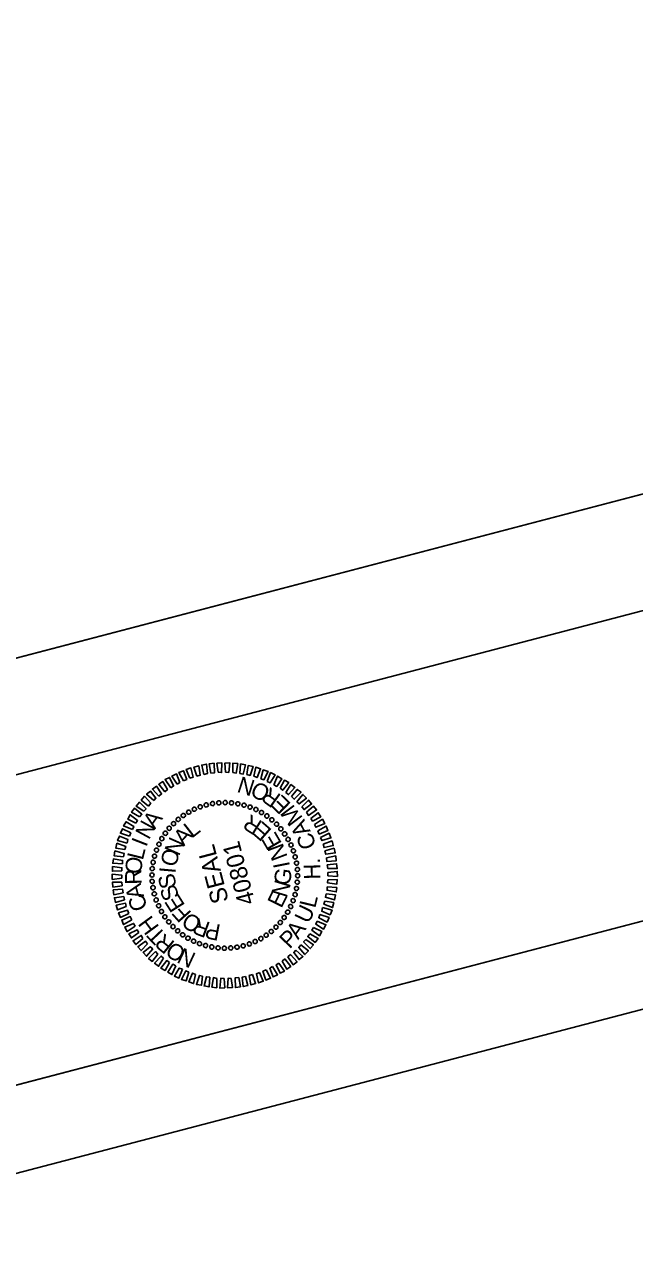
# Model space of a CAD drawing. Extents: x 1366394 to 1367903, y 879298 to 881221.
# Drawn here: x 1366670 to 1366872.8, y 880808.9 to 881221.1 of the extents above; entities that cross this region are included whole.
import ezdxf

# ---------------------------------------------------------------- set-up
doc = ezdxf.new("R2010")
doc.units = 0
for name, color, linetype in [('Exist Property Line Text', 7, 'Continuous'), ('Exist Right of Way Line', 7, 'Continuous'), ('Exist Structure Minor Footbridge Terminator', 7, 'Continuous'), ('Exist Structure Minor Pipes RCP 12 Inch', 7, 'Continuous'), ('Scratch_Level_0', 7, 'Continuous'), ('Scratch_Level_4', 7, 'Continuous')]:
    doc.layers.add(name, color=color, linetype=linetype)

msp = doc.modelspace()

# ---------------------------------------------------------------- linework, layer by layer
at = {"layer": 'Exist Property Line Text'}
msp.add_line((1367471.6, 881221.14), (1366407.53, 880942.29), dxfattribs=at)
at = {"layer": 'Exist Right of Way Line'}
for p, q in [((1367444.83, 881175.34), (1366453.31, 880915.52)), ((1367470.18, 881078.61), (1366478.66, 880818.79))]:
    msp.add_line(p, q, dxfattribs=at)
at = {"layer": 'Exist Structure Minor Footbridge Terminator'}
msp.add_lwpolyline([(1366869.99, 879396.08), (1366503.15, 880795.86), (1367465.82, 881048.15), (1367814.91, 879716.05)], close=True, dxfattribs=at)
at = {"layer": 'Exist Structure Minor Pipes RCP 12 Inch'}
for p, q in [((1366724.52, 880959.08), (1366724.52, 880959.08)), ((1366726.46, 880960.03), (1366726.46, 880960.03)), ((1366728.38, 880960.87), (1366728.38, 880960.87)), ((1366730.42, 880961.49), (1366730.42, 880961.49)), ((1366732.5, 880961.92), (1366732.5, 880961.92)), ((1366734.6, 880962.16), (1366734.6, 880962.16)), ((1366736.67, 880962.29), (1366736.67, 880962.29)), ((1366738.8, 880962.19), (1366738.8, 880962.19)), ((1366740.9, 880961.87), (1366740.9, 880961.87)), ((1366742.98, 880961.45), (1366742.98, 880961.45)), ((1366744.98, 880960.76), (1366744.98, 880960.76)), ((1366746.96, 880959.96), (1366746.96, 880959.96)), ((1366748.79, 880958.97), (1366748.79, 880958.97)), ((1366719.52, 880955.27), (1366719.52, 880955.27)), ((1366721.07, 880956.71), (1366721.07, 880956.71)), ((1366722.72, 880957.98), (1366722.72, 880957.98)), ((1366750.62, 880957.83), (1366750.62, 880957.83)), ((1366752.24, 880956.53), (1366752.24, 880956.53)), ((1366753.8, 880955.06), (1366753.8, 880955.06)), ((1366716.75, 880952.08), (1366716.75, 880952.08)), ((1366718.05, 880953.7), (1366718.05, 880953.7)), ((1366755.24, 880953.51), (1366755.24, 880953.51)), ((1366756.51, 880951.86), (1366756.51, 880951.86)), ((1366713.82, 880946.44), (1366713.82, 880946.44)), ((1366714.62, 880948.42), (1366714.62, 880948.42)), ((1366715.61, 880950.26), (1366715.61, 880950.26)), ((1366757.62, 880950.06), (1366757.62, 880950.06)), ((1366758.57, 880948.11), (1366758.57, 880948.11)), ((1366759.41, 880946.2), (1366759.41, 880946.2)), ((1366712.7, 880942.36), (1366712.7, 880942.36)), ((1366713.13, 880944.44), (1366713.13, 880944.44)), ((1366760.03, 880944.16), (1366760.03, 880944.16)), ((1366760.46, 880942.07), (1366760.46, 880942.07)), ((1366712.29, 880938.13), (1366712.29, 880938.13)), ((1366712.39, 880940.27), (1366712.39, 880940.27)), ((1366736.56, 880938.02), (1366736.56, 880938.02)), ((1366760.7, 880939.98), (1366760.7, 880939.98)), ((1366712.42, 880936.06), (1366712.42, 880936.06)), ((1366712.65, 880933.97), (1366712.65, 880933.97)), ((1366760.73, 880935.77), (1366760.73, 880935.77)), ((1366760.83, 880937.91), (1366760.83, 880937.91)), ((1366713.09, 880931.88), (1366713.09, 880931.88)), ((1366713.71, 880929.85), (1366713.71, 880929.85)), ((1366759.99, 880931.6), (1366759.99, 880931.6)), ((1366760.41, 880933.68), (1366760.41, 880933.68)), ((1366714.55, 880927.93), (1366714.55, 880927.93)), ((1366715.5, 880925.98), (1366715.5, 880925.98)), ((1366757.51, 880925.79), (1366757.51, 880925.79)), ((1366758.5, 880927.62), (1366758.5, 880927.62)), ((1366759.3, 880929.6), (1366759.3, 880929.6)), ((1366716.6, 880924.19), (1366716.6, 880924.19)), ((1366717.87, 880922.54), (1366717.87, 880922.54)), ((1366755.06, 880922.34), (1366755.06, 880922.34)), ((1366756.37, 880923.96), (1366756.37, 880923.96)), ((1366719.31, 880920.98), (1366719.31, 880920.98)), ((1366720.88, 880919.51), (1366720.88, 880919.51)), ((1366722.5, 880918.21), (1366722.5, 880918.21)), ((1366750.39, 880918.07), (1366750.39, 880918.07)), ((1366752.04, 880919.33), (1366752.04, 880919.33)), ((1366753.6, 880920.77), (1366753.6, 880920.77)), ((1366724.32, 880917.07), (1366724.32, 880917.07)), ((1366726.16, 880916.08), (1366726.16, 880916.08)), ((1366728.14, 880915.28), (1366728.14, 880915.28)), ((1366730.14, 880914.59), (1366730.14, 880914.59)), ((1366732.22, 880914.17), (1366732.22, 880914.17)), ((1366734.31, 880913.85), (1366734.31, 880913.85)), ((1366736.45, 880913.75), (1366736.45, 880913.75)), ((1366738.52, 880913.88), (1366738.52, 880913.88)), ((1366740.61, 880914.12), (1366740.61, 880914.12)), ((1366742.7, 880914.55), (1366742.7, 880914.55)), ((1366744.73, 880915.17), (1366744.73, 880915.17)), ((1366746.65, 880916.01), (1366746.65, 880916.01)), ((1366748.6, 880916.96), (1366748.6, 880916.96))]:
    msp.add_line(p, q, dxfattribs=at)
for points in [[(1366729.62, 880971.65), (1366728.87, 880974.71), (1366730.43, 880975.04), (1366730.76, 880971.88)], [(1366731.92, 880972.05), (1366731.36, 880975.1), (1366733, 880975.36), (1366733.1, 880972.13)], [(1366734.4, 880972.35), (1366733.96, 880975.33), (1366735.63, 880975.45), (1366735.48, 880972.25)], [(1366736.8, 880972.37), (1366736.6, 880975.42), (1366738.22, 880975.53), (1366737.88, 880972.27)], [(1366739.23, 880972.3), (1366739.26, 880975.42), (1366740.87, 880975.21), (1366740.35, 880972.06)], [(1366741.54, 880971.94), (1366741.8, 880975.13), (1366743.43, 880974.83), (1366742.69, 880971.76)], [(1366720.7, 880968.4), (1366718.99, 880971.08), (1366720.5, 880971.8), (1366721.6, 880968.95)], [(1366722.82, 880969.45), (1366721.32, 880972.28), (1366722.86, 880972.87), (1366723.88, 880969.94)], [(1366724.97, 880970.35), (1366723.75, 880973.27), (1366725.3, 880973.8), (1366726.06, 880970.76)], [(1366727.28, 880971.05), (1366726.29, 880974.03), (1366727.88, 880974.48), (1366728.4, 880971.36)], [(1366743.94, 880971.61), (1366744.36, 880974.59), (1366746, 880974.3), (1366744.98, 880971.3)], [(1366746.25, 880971.06), (1366746.92, 880974.05), (1366748.48, 880973.49), (1366747.3, 880970.55)], [(1366748.5, 880970.18), (1366749.38, 880973.14), (1366750.98, 880972.63), (1366749.56, 880969.83)], [(1366750.66, 880969.29), (1366751.8, 880972.21), (1366753.3, 880971.53), (1366751.68, 880968.87)], [(1366752.89, 880968.15), (1366754.13, 880971.06), (1366755.53, 880970.2), (1366753.84, 880967.62)], [(1366714.65, 880964.39), (1366712.48, 880966.74), (1366713.8, 880967.77), (1366715.54, 880965.14)], [(1366716.6, 880965.84), (1366714.59, 880968.34), (1366715.89, 880969.26), (1366717.45, 880966.58)], [(1366718.62, 880967.21), (1366716.72, 880969.89), (1366718.18, 880970.6), (1366719.51, 880967.81)], [(1366754.95, 880967.08), (1366756.42, 880969.7), (1366757.85, 880968.89), (1366755.85, 880966.37)], [(1366756.91, 880965.62), (1366758.58, 880968.25), (1366759.91, 880967.26), (1366757.77, 880964.91)], [(1366711.2, 880961.11), (1366708.74, 880963.08), (1366709.89, 880964.36), (1366711.95, 880962.03)], [(1366712.91, 880962.9), (1366710.55, 880965.05), (1366711.82, 880966.06), (1366713.64, 880963.7)], [(1366758.8, 880964.24), (1366760.69, 880966.63), (1366761.92, 880965.67), (1366759.65, 880963.38)], [(1366760.54, 880962.52), (1366762.57, 880964.95), (1366763.72, 880963.71), (1366761.35, 880961.79)], [(1366762.22, 880960.83), (1366764.41, 880963.06), (1366765.46, 880961.8), (1366762.93, 880959.93)], [(1366708.21, 880957.46), (1366705.52, 880959.02), (1366706.5, 880960.34), (1366708.96, 880958.38)], [(1366709.63, 880959.37), (1366707.04, 880961.1), (1366708.14, 880962.36), (1366710.36, 880960.18)], [(1366763.77, 880959.06), (1366766.13, 880961.03), (1366767.08, 880959.79), (1366764.38, 880957.98)], [(1366765.16, 880956.99), (1366767.65, 880958.85), (1366768.47, 880957.52), (1366765.76, 880956.1)], [(1366705.84, 880953.24), (1366702.88, 880954.46), (1366703.69, 880955.89), (1366706.29, 880954.31)], [(1366706.99, 880955.36), (1366704.25, 880956.75), (1366705.05, 880958.18), (1366707.54, 880956.27)], [(1366766.39, 880954.93), (1366769.04, 880956.73), (1366769.81, 880955.24), (1366766.9, 880954.02)], [(1366704.03, 880948.76), (1366700.88, 880949.63), (1366701.51, 880951.12), (1366704.3, 880949.94)], [(1366704.89, 880951.06), (1366701.85, 880952.06), (1366702.53, 880953.56), (1366705.29, 880952.13)], [(1366767.53, 880952.84), (1366770.29, 880954.42), (1366770.86, 880952.92), (1366767.98, 880951.76)], [(1366768.43, 880950.68), (1366771.27, 880952.03), (1366771.9, 880950.51), (1366768.89, 880949.61)], [(1366703.28, 880946.6), (1366700.28, 880947.11), (1366700.68, 880948.72), (1366703.59, 880947.64)], [(1366769.32, 880948.43), (1366772.28, 880949.51), (1366772.66, 880947.96), (1366769.59, 880947.3)], [(1366769.9, 880946.18), (1366772.92, 880947.03), (1366773.31, 880945.48), (1366770.16, 880945.05)], [(1366702.52, 880941.81), (1366699.29, 880942.06), (1366699.48, 880943.52), (1366702.54, 880942.98)], [(1366702.82, 880944.15), (1366699.74, 880944.55), (1366699.99, 880946.17), (1366703.04, 880945.32)], [(1366770.41, 880943.82), (1366773.49, 880944.48), (1366773.64, 880942.87), (1366770.54, 880942.64)], [(1366702.29, 880937.08), (1366699.14, 880936.7), (1366699.07, 880938.39), (1366702.25, 880938.13)], [(1366702.27, 880939.49), (1366699.19, 880939.37), (1366699.25, 880940.95), (1366702.32, 880940.55)], [(1366770.67, 880941.48), (1366773.76, 880941.89), (1366773.96, 880940.29), (1366770.84, 880940.32)], [(1366770.82, 880938.96), (1366773.98, 880939.34), (1366774.05, 880937.66), (1366770.86, 880937.92)], [(1366702.45, 880934.57), (1366699.35, 880934.15), (1366699.15, 880935.75), (1366702.27, 880935.72)], [(1366770.59, 880934.23), (1366773.83, 880933.98), (1366773.63, 880932.52), (1366770.57, 880933.07)], [(1366770.84, 880936.56), (1366773.92, 880936.67), (1366773.86, 880935.1), (1366770.79, 880935.49)], [(1366702.7, 880932.23), (1366699.63, 880931.57), (1366699.47, 880933.18), (1366702.57, 880933.4)], [(1366703.21, 880929.86), (1366700.19, 880929.02), (1366699.81, 880930.56), (1366702.95, 880930.99)], [(1366770.3, 880931.89), (1366773.37, 880931.5), (1366773.12, 880929.87), (1366770.07, 880930.72)], [(1366703.8, 880927.62), (1366700.84, 880926.54), (1366700.45, 880928.08), (1366703.53, 880928.75)], [(1366704.68, 880925.36), (1366701.85, 880924.01), (1366701.22, 880925.54), (1366704.23, 880926.43)], [(1366769.08, 880927.28), (1366772.24, 880926.41), (1366771.6, 880924.93), (1366768.81, 880926.1)], [(1366769.83, 880929.45), (1366772.83, 880928.94), (1366772.44, 880927.32), (1366769.52, 880928.41)], [(1366705.59, 880923.2), (1366702.82, 880921.62), (1366702.25, 880923.12), (1366705.13, 880924.28)], [(1366706.73, 880921.11), (1366704.07, 880919.31), (1366703.3, 880920.8), (1366706.22, 880922.02)], [(1366767.28, 880922.81), (1366770.23, 880921.58), (1366769.43, 880920.15), (1366766.83, 880921.73)], [(1366768.22, 880924.98), (1366771.26, 880923.98), (1366770.58, 880922.48), (1366767.82, 880923.91)], [(1366707.96, 880919.05), (1366705.47, 880917.2), (1366704.65, 880918.52), (1366707.36, 880919.94)], [(1366709.34, 880916.98), (1366706.99, 880915.01), (1366706.03, 880916.25), (1366708.74, 880918.06)], [(1366764.9, 880918.58), (1366767.6, 880917.03), (1366766.61, 880915.7), (1366764.15, 880917.67)], [(1366766.12, 880920.68), (1366768.87, 880919.29), (1366768.07, 880917.86), (1366765.57, 880919.77)], [(1366710.89, 880915.21), (1366708.71, 880912.99), (1366707.65, 880914.25), (1366710.19, 880916.11)], [(1366712.57, 880913.52), (1366710.54, 880911.09), (1366709.4, 880912.33), (1366711.77, 880914.25)], [(1366761.91, 880914.93), (1366764.37, 880912.96), (1366763.23, 880911.68), (1366761.17, 880914.02)], [(1366763.48, 880916.67), (1366766.07, 880914.94), (1366764.97, 880913.68), (1366762.75, 880915.87)], [(1366714.31, 880911.8), (1366712.42, 880909.41), (1366711.2, 880910.38), (1366713.47, 880912.67)], [(1366716.2, 880910.42), (1366714.53, 880907.8), (1366713.2, 880908.78), (1366715.35, 880911.14)], [(1366718.17, 880908.97), (1366716.7, 880906.35), (1366715.27, 880907.15), (1366717.27, 880909.67)], [(1366756.52, 880910.2), (1366758.52, 880907.7), (1366757.22, 880906.79), (1366755.67, 880909.46)], [(1366758.47, 880911.65), (1366760.63, 880909.3), (1366759.31, 880908.28), (1366757.57, 880910.9)], [(1366760.21, 880913.14), (1366762.57, 880911), (1366761.29, 880909.99), (1366759.48, 880912.34)], [(1366720.23, 880907.89), (1366718.98, 880904.98), (1366717.59, 880905.84), (1366719.27, 880908.43)], [(1366722.45, 880906.76), (1366721.32, 880903.83), (1366719.82, 880904.52), (1366721.43, 880907.17)], [(1366724.61, 880905.86), (1366723.73, 880902.9), (1366722.14, 880903.41), (1366723.56, 880906.22)], [(1366726.86, 880904.99), (1366726.2, 880901.99), (1366724.63, 880902.55), (1366725.82, 880905.5)], [(1366745.83, 880904.99), (1366746.82, 880902.01), (1366745.24, 880901.57), (1366744.72, 880904.68)], [(1366748.15, 880905.69), (1366749.37, 880902.77), (1366747.81, 880902.24), (1366747.06, 880905.29)], [(1366750.3, 880906.6), (1366751.8, 880903.76), (1366750.26, 880903.17), (1366749.24, 880906.1)], [(1366752.42, 880907.64), (1366754.12, 880904.96), (1366752.62, 880904.24), (1366751.52, 880907.09)], [(1366754.49, 880908.83), (1366756.4, 880906.15), (1366754.94, 880905.44), (1366753.61, 880908.23)], [(1366729.18, 880904.43), (1366728.76, 880901.45), (1366727.12, 880901.75), (1366728.14, 880904.74)], [(1366731.58, 880904.1), (1366731.32, 880900.92), (1366729.68, 880901.21), (1366730.43, 880904.28)], [(1366733.88, 880903.75), (1366733.86, 880900.63), (1366732.25, 880900.83), (1366732.76, 880903.98)], [(1366736.32, 880903.68), (1366736.52, 880900.62), (1366734.89, 880900.52), (1366735.23, 880903.77)], [(1366738.72, 880903.7), (1366739.16, 880900.71), (1366737.48, 880900.59), (1366737.64, 880903.8)], [(1366741.19, 880903.99), (1366741.75, 880900.94), (1366740.12, 880900.68), (1366740.01, 880903.91)], [(1366743.49, 880904.39), (1366744.25, 880901.34), (1366742.69, 880901), (1366742.35, 880904.16)]]:
    msp.add_lwpolyline(points, close=True, dxfattribs=at)
for centre, major_axis in [((1366734.58, 880962.17), (-0.057, 0.693)), ((1366736.69, 880962.25), (0.004, 0.696)), ((1366738.8, 880962.15), (0.064, 0.693)), ((1366722.77, 880957.95), (-0.396, 0.572)), ((1366724.55, 880959.07), (-0.345, 0.604)), ((1366726.44, 880960.04), (-0.291, 0.632)), ((1366728.39, 880960.84), (-0.234, 0.655)), ((1366730.41, 880961.46), (-0.176, 0.673)), ((1366732.48, 880961.91), (-0.117, 0.686)), ((1366740.9, 880961.86), (0.125, 0.685)), ((1366742.96, 880961.39), (0.184, 0.671)), ((1366744.97, 880960.75), (0.242, 0.652)), ((1366746.92, 880959.93), (0.298, 0.629)), ((1366748.79, 880958.94), (0.351, 0.601)), ((1366750.57, 880957.79), (0.402, 0.568)), ((1366718.08, 880953.7), (-0.531, 0.45)), ((1366719.51, 880955.25), (-0.489, 0.495)), ((1366721.08, 880956.67), (-0.444, 0.535)), ((1366752.24, 880956.5), (0.45, 0.531)), ((1366753.79, 880955.06), (0.495, 0.489)), ((1366715.64, 880950.25), (-0.601, 0.351)), ((1366716.78, 880952.03), (-0.568, 0.402)), ((1366755.21, 880953.49), (0.535, 0.444)), ((1366756.49, 880951.81), (0.572, 0.396)), ((1366757.61, 880950.02), (0.604, 0.345)), ((1366713.83, 880946.43), (-0.652, 0.242)), ((1366714.65, 880948.38), (-0.629, 0.298)), ((1366758.58, 880948.14), (0.632, 0.291)), ((1366759.38, 880946.18), (0.655, 0.234)), ((1366712.71, 880942.36), (-0.685, 0.125)), ((1366713.18, 880944.42), (-0.671, 0.184)), ((1366760, 880944.16), (0.673, 0.176)), ((1366760.45, 880942.1), (0.686, 0.117)), ((1366712.32, 880938.15), (-0.696, 0.004)), ((1366712.43, 880940.26), (-0.693, 0.064)), ((1366760.71, 880940), (0.693, 0.057)), ((1366760.79, 880937.89), (0.696, -0.004)), ((1366712.4, 880936.04), (-0.693, -0.057)), ((1366712.67, 880933.94), (-0.686, -0.117)), ((1366760.4, 880933.68), (0.685, -0.125)), ((1366760.69, 880935.77), (0.693, -0.064)), ((1366713.11, 880931.87), (-0.673, -0.176)), ((1366713.74, 880929.85), (-0.655, -0.234)), ((1366759.29, 880929.6), (0.652, -0.242)), ((1366759.93, 880931.62), (0.671, -0.184)), ((1366714.54, 880927.9), (-0.632, -0.291)), ((1366715.5, 880926.02), (-0.604, -0.345)), ((1366757.48, 880925.79), (0.601, -0.351)), ((1366758.47, 880927.66), (0.629, -0.298)), ((1366716.63, 880924.23), (-0.572, -0.396)), ((1366717.91, 880922.54), (-0.535, -0.444)), ((1366719.33, 880920.98), (-0.495, -0.489)), ((1366753.6, 880920.79), (0.489, -0.495)), ((1366755.04, 880922.34), (0.531, -0.45)), ((1366756.33, 880924.01), (0.568, -0.402)), ((1366720.88, 880919.54), (-0.45, -0.531)), ((1366722.55, 880918.24), (-0.402, -0.568)), ((1366724.32, 880917.1), (-0.351, -0.601)), ((1366748.56, 880916.96), (0.345, -0.604)), ((1366750.35, 880918.09), (0.396, -0.572)), ((1366752.03, 880919.37), (0.444, -0.535)), ((1366726.19, 880916.11), (-0.298, -0.629)), ((1366728.14, 880915.29), (-0.242, -0.652)), ((1366730.16, 880914.64), (-0.184, -0.671)), ((1366732.22, 880914.17), (-0.125, -0.685)), ((1366734.31, 880913.89), (-0.064, -0.693)), ((1366736.42, 880913.78), (-0.004, -0.696)), ((1366738.54, 880913.86), (0.057, -0.693)), ((1366740.63, 880914.13), (0.117, -0.686)), ((1366742.7, 880914.57), (0.176, -0.673)), ((1366744.72, 880915.2), (0.234, -0.655)), ((1366746.68, 880916), (0.291, -0.632))]:
    msp.add_ellipse(centre, major_axis=major_axis, ratio=0.999708, dxfattribs=at)
at = {"layer": 'Scratch_Level_0'}
msp.add_lwpolyline([(1366865.26, 879343.61), (1366478.66, 880818.79), (1367470.18, 881078.63), (1367856.77, 879603.45)], close=True, dxfattribs=at)
at = {"layer": 'Scratch_Level_4'}
msp.add_lwpolyline([(1366838.49, 879297.82), (1366407.53, 880942.29), (1367471.6, 881221.14), (1367902.56, 879576.68)], close=True, dxfattribs=at)

# ---------------------------------------------------------------- texts
at = {"layer": 'Exist Structure Minor Pipes RCP 12 Inch'}
for s, height, rotation, p in [('N', 5.46, 162.2488, (1366747, 880969.47)), ('O', 5.46, 153.3152, (1366752.15, 880967.07)), ('R', 5.46, 144.3093, (1366755.59, 880964.61)), ('E', 5.46, 135.9223, (1366758.88, 880961.8)), ('A', 5.45, 54.3023, (1366713.29, 880953.16)), ('M', 5.46, 126.9479, (1366762.71, 880957.12)), ('N', 5.45, 61.504, (1366711.31, 880949.64)), ('L', 5.45, 38.086, (1366725.65, 880950.26)), ('R', 5.45, 148.1665, (1366749.39, 880955.77)), ('E', 5.45, 138.8092, (1366752.5, 880953.08)), ('A', 5.46, 118.0142, (1366765.21, 880952.7)), ('I', 5.45, 68.7053, (1366710.43, 880947.24)), ('N', 5.45, 66.1617, (1366721.27, 880944.21)), ('A', 5.45, 47.4454, (1366722.94, 880947.54)), ('E', 5.45, 120.0969, (1366755.7, 880948.66)), ('C', 5.46, 109.0084, (1366767.11, 880947.75)), ('L', 5.45, 75.906, (1366709.26, 880942.84)), ('O', 5.45, 75.5186, (1366720.28, 880940.57)), ('SEAL', 5.796, 104.8532, (1366737.94, 880929.53)), ('SEAL', 5.796, 104.6851, (1366737.94, 880929.52)), ('40801', 5.798, 104.6851, (1366746.73, 880929.01)), ('N', 5.45, 110.7415, (1366757.55, 880944.21)), ('O', 5.45, 83.1063, (1366708.69, 880938.27)), ('I', 5.45, 101.3863, (1366758.29, 880941.05)), ('H.', 5.46, 90.9953, (1366768.38, 880936.67)), ('R', 5.45, 90.3062, (1366708.86, 880934.95)), ('S', 5.45, 103.5855, (1366720.63, 880934.34)), ('I', 5.45, 84.8747, (1366720.15, 880938.52)), ('G', 5.45, 82.6754, (1366758.23, 880934.47)), ('A', 5.45, 104.7054, (1366709.78, 880930.99)), ('S', 5.45, 112.9407, (1366721.61, 880931.01)), ('N', 5.45, 73.3191, (1366757.13, 880930.34)), ('C', 5.45, 111.905, (1366711.08, 880927.4)), ('E', 5.45, 122.2962, (1366723.49, 880928.07)), ('E', 5.45, 63.962, (1366755.41, 880926.84)), ('L', 5.46, 76.2009, (1366766.63, 880926.89)), ('F', 5.45, 131.6521, (1366725.72, 880925.49)), ('U', 5.46, 64.4578, (1366764.45, 880921.68)), ('H', 5.45, 126.3046, (1366714.93, 880920.85)), ('O', 5.45, 150.3664, (1366729.33, 880923.19)), ('R', 5.45, 159.7248, (1366732.07, 880922.2)), ('P', 5.45, 169.084, (1366735.46, 880921.55)), ('A', 5.46, 53.7081, (1366760.96, 880916.43)), ('T', 5.45, 133.5049, (1366717.31, 880918.26)), ('R', 5.45, 140.7056, (1366720.25, 880915.67)), ('P', 5.46, 46.3622, (1366758.12, 880913.34)), ('O', 5.45, 147.9069, (1366724.04, 880913.27)), ('N', 5.45, 155.1086, (1366727.34, 880911.89))]:
    msp.add_text(s, height=height, rotation=rotation, dxfattribs=at).set_placement(p)

doc.saveas('drawing.dxf')
